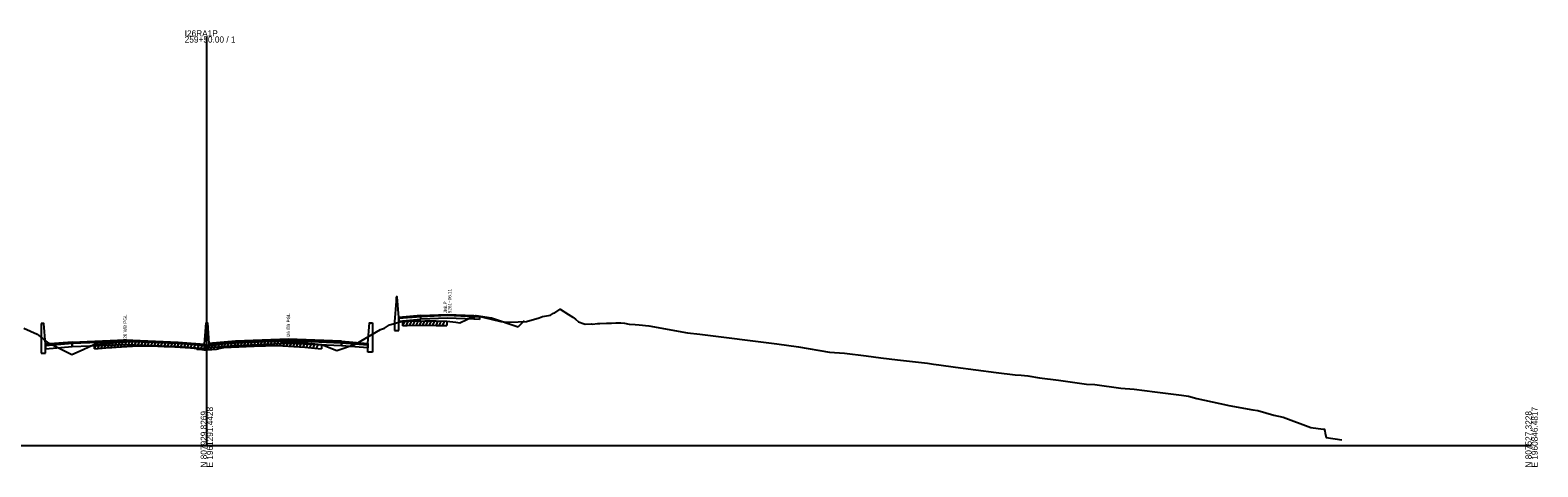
# Model space of a CAD drawing. Extents: x 1017 to 19997, y -1947 to 50737.
# Drawn here: x 10520 to 11203, y 9490 to 9688 of the extents above; entities that cross this region are included whole.
import ezdxf

# ---------------------------------------------------------------- set-up
doc = ezdxf.new("R2010")
doc.units = 0
for name, color, linetype in [('RD_GPK_XS_Cell', 7, 'Continuous'), ('RD_XS_Base', 7, 'Continuous'), ('RD_XS_ExGround', 7, 'Continuous'), ('RD_XS_ExPaveRet', 7, 'Continuous'), ('RD_XS_Greenside', 7, 'Continuous'), ('RD_XS_MedBWall', 7, 'Continuous'), ('RD_XS_Pave', 7, 'Continuous'), ('RD_XS_PaveOvlay', 7, 'Continuous'), ('RD_XS_TieSlope', 7, 'Continuous'), ('RD_XS_TX_Notes', 7, 'Continuous')]:
    doc.layers.add(name, color=color, linetype=linetype)

msp = doc.modelspace()

# ---------------------------------------------------------------- linework, layer by layer
at = {"layer": 'RD_GPK_XS_Cell'}
for p, q in [((10600, 9500), (10600, 9685.34)), ((10000, 9500), (10600, 9500)), ((10600, 9500), (11200, 9500))]:
    msp.add_line(p, q, dxfattribs=at)
at = {"layer": 'RD_XS_Base'}
for points in [[(10697, 9558.51), (10687, 9557.71)], [(10687, 9557.71), (10687, 9556.38)], [(10687, 9556.38), (10697, 9557.18)], [(10697, 9558.51), (10709, 9558.99), (10721, 9558.51)], [(10697, 9557.18), (10697, 9558.51)], [(10721, 9557.2), (10709, 9557.66), (10697, 9557.18)], [(10721, 9558.51), (10721, 9557.2)], [(10721, 9558.51), (10723, 9558.43), (10723.5, 9558.41)], [(10723.5, 9557.08), (10721, 9557.2)], [(10723.5, 9558.41), (10723.5, 9557.08)], [(10539, 9546.16), (10527, 9545.2)], [(10539, 9544.82), (10539, 9546.16)], [(10539.05, 9546.16), (10539.05, 9544.82)], [(10587, 9544.83), (10587, 9546.17)], [(10599, 9545.23), (10587, 9546.17)], [(10613, 9545.22), (10613, 9546.56)], [(10660.95, 9545.22), (10637, 9546.19), (10613, 9545.22)], [(10660.95, 9545.22), (10660.95, 9546.56)], [(10661, 9546.56), (10661, 9545.22)], [(10661, 9546.55), (10673, 9545.59)], [(10661, 9545.21), (10661, 9546.55)], [(10527, 9545.2), (10527, 9543.86)], [(10527, 9543.86), (10539, 9544.82)], [(10539.05, 9544.82), (10539, 9544.82)], [(10539.05, 9544.82), (10563, 9545.79), (10587, 9544.83)], [(10587, 9544.83), (10599, 9543.89)], [(10599, 9543.89), (10599, 9545.23)], [(10601, 9544.28), (10601, 9545.62)], [(10613, 9545.22), (10601, 9544.28)], [(10661, 9545.22), (10660.95, 9545.22)], [(10673, 9544.25), (10661, 9545.21)], [(10673, 9545.59), (10673, 9544.25)]]:
    msp.add_lwpolyline(points, dxfattribs=at)
at = {"layer": 'RD_XS_ExGround'}
msp.add_lwpolyline([(10517.09, 9553.15), (10523.18, 9550.47), (10527.73, 9546.79), (10538.86, 9541.28), (10542.6, 9542.88), (10547.87, 9545.3), (10549.14, 9545.86), (10556.05, 9546.38), (10557.06, 9546.46), (10558.91, 9546.58), (10568.7, 9547.2), (10577.84, 9546.97), (10580.7, 9546.89), (10583.05, 9546.77), (10592.56, 9546.27), (10593.25, 9546.19), (10595.4, 9545.95), (10595.53, 9545.66), (10597.78, 9545.44), (10598.6, 9545.39), (10599.34, 9545.38), (10600, 9545.39), (10601.38, 9545.41), (10602.28, 9545.49), (10604.43, 9545.65), (10605.26, 9545.76), (10605.4, 9546.05), (10606.15, 9546.13), (10607.67, 9546.33), (10617.87, 9546.88), (10619.85, 9546.99), (10621.42, 9547.02), (10631.89, 9547.25), (10634.51, 9547.11), (10644.47, 9546.54), (10650.37, 9545.96), (10652, 9545.79), (10652.44, 9545.64), (10658.9, 9542.99), (10667.39, 9545.97), (10678.71, 9552.59), (10680.47, 9553.13), (10682.8, 9554.64), (10687.56, 9555.96), (10688.81, 9556.21), (10690.77, 9556.31), (10698.73, 9556.53), (10703.85, 9556.42), (10708.79, 9556.37), (10712.81, 9555.82), (10714.63, 9555.58), (10720.97, 9558.59), (10721.86, 9558.85), (10733.12, 9556.22), (10736.41, 9555.83), (10737.24, 9555.86), (10744.87, 9556.23), (10750.56, 9557.82), (10752, 9558.39), (10755.62, 9559.08), (10757.07, 9559.98), (10757.65, 9560.12), (10760.09, 9561.78), (10763.88, 9559.37), (10765.83, 9558.07), (10767, 9557.2), (10768.3, 9555.98), (10770.89, 9555.07), (10771.3, 9554.89), (10774.16, 9555.05), (10774.65, 9555), (10776.95, 9555.28), (10778.05, 9555.25), (10781.07, 9555.43), (10783.28, 9555.41), (10785.21, 9555.54), (10787.48, 9555.54), (10789.12, 9555.42), (10791.31, 9555.03), (10793.94, 9554.75), (10795.81, 9554.64), (10800.23, 9554.2), (10817.69, 9550.99), (10823.35, 9550.4), (10858.14, 9546.07), (10868.06, 9544.7), (10882.07, 9542.3), (10888.87, 9541.8), (10898.6, 9540.59), (10905.34, 9539.74), (10912.79, 9538.86), (10926.37, 9537.26), (10929.07, 9536.82), (10931.6, 9536.52), (10939.05, 9535.47), (10957.51, 9532.99), (10966.13, 9532.02), (10968.79, 9531.8), (10971.9, 9531.49), (10977.2, 9530.64), (10985.72, 9529.56), (10998.47, 9527.84), (11002.23, 9527.6), (11014.04, 9526.02), (11019.96, 9525.48), (11029.3, 9524.3), (11041.41, 9522.73), (11044.64, 9522.39), (11048.44, 9521.29), (11062.21, 9518.33), (11062.84, 9518.11), (11073.8, 9516.09), (11076.06, 9515.81), (11083.24, 9513.8), (11087.5, 9512.77), (11099.97, 9508.15), (11105.67, 9507.4), (11106.28, 9507.4), (11106.48, 9505.55), (11106.94, 9503.56), (11114.07, 9502.6)], dxfattribs=at)
at = {"layer": 'RD_XS_ExPaveRet'}
for p, q in [((10688.81, 9554.21), (10689.84, 9556.27)), ((10688.81, 9554.21), (10688.81, 9556.21)), ((10688.81, 9554.21), (10690.77, 9554.31)), ((10690.31, 9554.29), (10691.33, 9556.33)), ((10690.77, 9554.31), (10698.73, 9554.53)), ((10691.81, 9554.34), (10692.82, 9556.37)), ((10693.31, 9554.38), (10694.32, 9556.41)), ((10694.81, 9554.42), (10695.82, 9556.45)), ((10696.31, 9554.46), (10697.32, 9556.49)), ((10697.81, 9554.5), (10698.82, 9556.53)), ((10698.73, 9554.53), (10703.85, 9554.42)), ((10699.31, 9554.52), (10700.3, 9556.5)), ((10700.81, 9554.49), (10701.8, 9556.47)), ((10702.31, 9554.46), (10703.3, 9556.44)), ((10703.81, 9554.43), (10704.8, 9556.41)), ((10703.85, 9554.42), (10708.79, 9554.37)), ((10705.31, 9554.41), (10706.3, 9556.4)), ((10706.81, 9554.39), (10707.8, 9556.38)), ((10708.79, 9556.37), (10708.79, 9554.37)), ((10552.14, 9544.09), (10553.18, 9546.17)), ((10553.64, 9544.2), (10554.68, 9546.28)), ((10555.14, 9544.31), (10556.18, 9546.39)), ((10556.64, 9544.43), (10557.67, 9546.5)), ((10558.14, 9544.53), (10559.17, 9546.6)), ((10559.64, 9544.63), (10560.67, 9546.7)), ((10561.14, 9544.72), (10562.17, 9546.79)), ((10562.64, 9544.82), (10563.67, 9546.88)), ((10564.14, 9544.91), (10565.17, 9546.98)), ((10565.64, 9545.01), (10566.67, 9547.07)), ((10567.14, 9545.1), (10568.17, 9547.17)), ((10568.64, 9545.2), (10569.63, 9547.18)), ((10570.14, 9545.17), (10571.12, 9547.14)), ((10571.64, 9545.13), (10572.62, 9547.1)), ((10573.14, 9545.09), (10574.12, 9547.06)), ((10574.64, 9545.05), (10575.62, 9547.03)), ((10576.14, 9545.01), (10577.12, 9546.99)), ((10577.64, 9544.97), (10578.62, 9546.95)), ((10579.14, 9544.93), (10580.12, 9546.9)), ((10580.64, 9544.89), (10581.61, 9546.84)), ((10582.14, 9544.81), (10583.11, 9546.76)), ((10583.64, 9544.74), (10584.61, 9546.69)), ((10585.14, 9544.66), (10586.11, 9546.61)), ((10586.64, 9544.58), (10587.61, 9546.53)), ((10588.14, 9544.5), (10589.11, 9546.45)), ((10589.64, 9544.42), (10590.61, 9546.37)), ((10591.14, 9544.34), (10592.11, 9546.29)), ((10592.64, 9544.26), (10593.58, 9546.15)), ((10604.64, 9543.67), (10605.85, 9546.1)), ((10606.14, 9544.13), (10607.21, 9546.27)), ((10607.64, 9544.33), (10608.66, 9546.39)), ((10609.14, 9544.41), (10610.16, 9546.47)), ((10610.64, 9544.49), (10611.66, 9546.55)), ((10612.14, 9544.57), (10613.16, 9546.63)), ((10613.64, 9544.65), (10614.66, 9546.71)), ((10615.14, 9544.74), (10616.16, 9546.79)), ((10616.64, 9544.82), (10617.66, 9546.87)), ((10618.14, 9544.9), (10619.16, 9546.95)), ((10619.64, 9544.98), (10620.65, 9547)), ((10621.14, 9545.01), (10622.15, 9547.04)), ((10622.64, 9545.05), (10623.65, 9547.07)), ((10624.14, 9545.08), (10625.15, 9547.1)), ((10625.64, 9545.11), (10626.65, 9547.13)), ((10627.14, 9545.14), (10628.15, 9547.17)), ((10628.64, 9545.18), (10629.65, 9547.2)), ((10630.14, 9545.21), (10631.15, 9547.23)), ((10631.64, 9545.24), (10632.62, 9547.21)), ((10633.14, 9545.18), (10634.11, 9547.13)), ((10634.64, 9545.1), (10635.61, 9547.04)), ((10636.14, 9545.01), (10637.11, 9546.96)), ((10637.64, 9544.93), (10638.61, 9546.87)), ((10639.14, 9544.84), (10640.11, 9546.79)), ((10640.64, 9544.76), (10641.61, 9546.7)), ((10642.14, 9544.67), (10643.11, 9546.62)), ((10643.64, 9544.59), (10644.61, 9546.53)), ((10645.14, 9544.48), (10646.09, 9546.38)), ((10646.64, 9544.33), (10647.59, 9546.24)), ((10549.14, 9543.86), (10550.18, 9545.94)), ((10549.14, 9543.86), (10549.14, 9545.86)), ((10549.14, 9543.86), (10556.05, 9544.38)), ((10550.64, 9543.97), (10551.68, 9546.05)), ((10556.05, 9544.38), (10557.06, 9544.46)), ((10557.06, 9544.46), (10558.91, 9544.58)), ((10558.91, 9544.58), (10568.7, 9545.2)), ((10568.7, 9545.2), (10577.84, 9544.97)), ((10577.84, 9544.97), (10580.7, 9544.89)), ((10580.7, 9544.89), (10583.05, 9544.77)), ((10583.05, 9544.77), (10592.56, 9544.27)), ((10592.56, 9544.27), (10593.25, 9544.19)), ((10593.25, 9544.19), (10595.4, 9543.95)), ((10594.14, 9544.09), (10595.08, 9545.99)), ((10595.4, 9543.95), (10595.53, 9543.66)), ((10595.53, 9543.66), (10597.78, 9543.44)), ((10595.64, 9543.65), (10596.59, 9545.56)), ((10597.14, 9543.51), (10598.09, 9545.42)), ((10597.78, 9543.44), (10598.6, 9543.39)), ((10598.6, 9543.39), (10599.34, 9543.38)), ((10598.64, 9543.39), (10599.63, 9545.38)), ((10599.34, 9543.38), (10600, 9543.39)), ((10600, 9543.39), (10601.38, 9543.41)), ((10600.14, 9543.39), (10601.15, 9545.41)), ((10601.38, 9543.41), (10602.28, 9543.49)), ((10601.64, 9543.44), (10602.68, 9545.52)), ((10602.28, 9543.49), (10604.43, 9543.65)), ((10603.14, 9543.55), (10604.17, 9545.63)), ((10604.43, 9543.65), (10605.26, 9543.76)), ((10605.26, 9543.76), (10605.4, 9544.05)), ((10605.4, 9544.05), (10606.15, 9544.13)), ((10606.15, 9544.13), (10607.67, 9544.33)), ((10607.67, 9544.33), (10617.87, 9544.88)), ((10617.87, 9544.88), (10619.85, 9544.99)), ((10619.85, 9544.99), (10621.42, 9545.02)), ((10621.42, 9545.02), (10631.89, 9545.25)), ((10631.89, 9545.25), (10634.51, 9545.11)), ((10634.51, 9545.11), (10644.47, 9544.54)), ((10644.47, 9544.54), (10650.37, 9543.96)), ((10648.14, 9544.18), (10649.09, 9546.09)), ((10649.64, 9544.04), (10650.59, 9545.94)), ((10650.37, 9543.96), (10652, 9543.79)), ((10652, 9545.79), (10652, 9543.79))]:
    msp.add_line(p, q, dxfattribs=at)
at = {"layer": 'RD_XS_Greenside'}
for points in [[(10723, 9558.75), (10729, 9557.79)], [(10729, 9557.79), (10741, 9553.78)]]:
    msp.add_lwpolyline(points, dxfattribs=at)
at = {"layer": 'RD_XS_MedBWall'}
for points in [[(10687, 9558.03), (10686.25, 9567.37), (10685.75, 9567.37)], [(10685.75, 9567.37), (10685.75, 9565.37)], [(10685.75, 9565.37), (10685, 9556.03)], [(10527, 9545.88), (10526.25, 9555.22), (10525, 9555.22)], [(10525, 9555.22), (10525, 9541.88)], [(10599, 9545.88), (10599.75, 9555.61), (10600.25, 9555.61), (10601, 9546.27)], [(10673, 9546.27), (10673.75, 9555.61), (10675, 9555.61)], [(10675, 9555.61), (10675, 9542.27)], [(10685, 9556.03), (10685, 9552.03)], [(10687, 9552.03), (10687, 9558.03)], [(10601, 9546.27), (10601, 9543.88)], [(10673, 9542.27), (10673, 9546.27)], [(10685, 9552.03), (10687, 9552.03)], [(10525, 9541.88), (10527, 9541.88)], [(10527, 9541.88), (10527, 9545.88)], [(10599, 9543.88), (10599, 9545.88)], [(10601, 9543.88), (10599, 9543.88)], [(10675, 9542.27), (10673, 9542.27)]]:
    msp.add_lwpolyline(points, dxfattribs=at)
at = {"layer": 'RD_XS_Pave'}
for points in [[(10539, 9546.5), (10527, 9545.54)], [(10539, 9546.16), (10539, 9546.5)], [(10539.05, 9546.16), (10539, 9546.16)], [(10539.05, 9546.5), (10563, 9547.47), (10587, 9546.51)], [(10587, 9546.17), (10563, 9547.13), (10539.05, 9546.16)], [(10539.05, 9546.16), (10539.05, 9546.5)], [(10587, 9546.51), (10587, 9546.17)], [(10587, 9546.51), (10599, 9545.57)], [(10613, 9546.9), (10601, 9545.96)], [(10601, 9545.62), (10613, 9546.56)], [(10660.95, 9546.9), (10637, 9547.86), (10613, 9546.9)], [(10613, 9546.56), (10637, 9547.53), (10660.95, 9546.56)], [(10613, 9546.9), (10613, 9546.56)], [(10660.95, 9546.56), (10660.95, 9546.9)], [(10660.95, 9546.9), (10661, 9546.9)], [(10661, 9546.56), (10660.95, 9546.56)], [(10661, 9546.9), (10661, 9546.56)], [(10661, 9546.55), (10661, 9546.89)], [(10527, 9545.54), (10527, 9545.2)], [(10599, 9545.57), (10599, 9545.23)], [(10601, 9545.96), (10601, 9545.62)], [(10673, 9545.93), (10673, 9545.59)]]:
    msp.add_lwpolyline(points, dxfattribs=at)
at = {"layer": 'RD_XS_PaveOvlay'}
for points in [[(10697, 9558.83), (10687, 9558.03)], [(10687, 9557.71), (10697, 9558.51)], [(10687, 9558.03), (10687, 9557.71)], [(10697, 9558.83), (10709, 9559.31), (10721, 9558.83)], [(10721, 9558.51), (10709, 9558.99), (10697, 9558.51)], [(10697, 9558.51), (10697, 9558.83)], [(10721, 9558.83), (10721, 9558.51)], [(10721, 9558.83), (10723, 9558.75)], [(10723, 9558.43), (10721, 9558.51)], [(10723, 9558.75), (10723, 9558.43)], [(10539, 9546.84), (10527, 9545.88)], [(10539.05, 9546.84), (10539, 9546.84)], [(10539, 9546.84), (10539, 9546.5)], [(10539, 9546.5), (10539.05, 9546.5)], [(10539.05, 9546.84), (10563, 9547.8), (10587, 9546.84)], [(10539.05, 9546.5), (10539.05, 9546.84)], [(10587, 9546.84), (10587, 9546.51)], [(10587, 9546.84), (10599, 9545.88)], [(10613, 9547.23), (10601, 9546.27)], [(10601, 9546.27), (10601, 9545.96)], [(10660.95, 9547.24), (10637, 9548.19), (10613, 9547.23)], [(10613, 9547.23), (10613, 9546.9)], [(10660.95, 9546.9), (10660.95, 9547.24)], [(10660.95, 9547.24), (10661, 9547.23)], [(10661, 9547.23), (10661, 9546.9)], [(10661, 9547.23), (10673, 9546.27)], [(10661, 9546.89), (10661, 9547.23)], [(10673, 9545.93), (10661, 9546.89)], [(10673, 9546.27), (10673, 9545.93)], [(10527, 9545.88), (10527, 9545.54)], [(10599, 9545.88), (10599, 9545.57)]]:
    msp.add_lwpolyline(points, dxfattribs=at)
at = {"layer": 'RD_XS_TieSlope'}
msp.add_lwpolyline([(10741, 9553.78), (10743.89, 9556.67)], dxfattribs=at)

# ---------------------------------------------------------------- texts
at = {"layer": 'RD_GPK_XS_Cell'}
for s, p in [('259+50.00 / 1', (10590, 9682.54)), ('I26RA1P', (10590, 9685.34))]:
    msp.add_text(s, height=2.8, dxfattribs=at).set_placement(p)
for s, p in [('N 807929.8269', (10600, 9490)), ('E 1961291.4428', (10602.8, 9490)), ('N 807527.3228', (11200, 9490)), ('E 1960846.4817', (11202.8, 9490))]:
    msp.add_text(s, height=2.8, rotation=90, dxfattribs=at).set_placement(p)
at = {"layer": 'RD_XS_TX_Notes'}
for s, p in [(' 9261+06.11', (10710.73, 9559.37)), (' JMLP', (10708.77, 9559.37)), ('I26 WB PGL', (10563.75, 9547.8)), ('I26 EB PGL', (10637.75, 9548.93))]:
    msp.add_text(s, height=1.5, rotation=90, dxfattribs=at).set_placement(p)

doc.saveas('drawing.dxf')
